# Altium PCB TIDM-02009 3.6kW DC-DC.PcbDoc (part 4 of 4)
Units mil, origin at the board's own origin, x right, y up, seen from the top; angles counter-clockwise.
Board outline 11220.47 x 8463 mil, 4 copper layers (Top Layer, Signal Layer 1, Signal Layer 2, Bottom Layer), stack 109.77 mil thick; 298 components, 250 nets, 959 pads, 2937 vias.
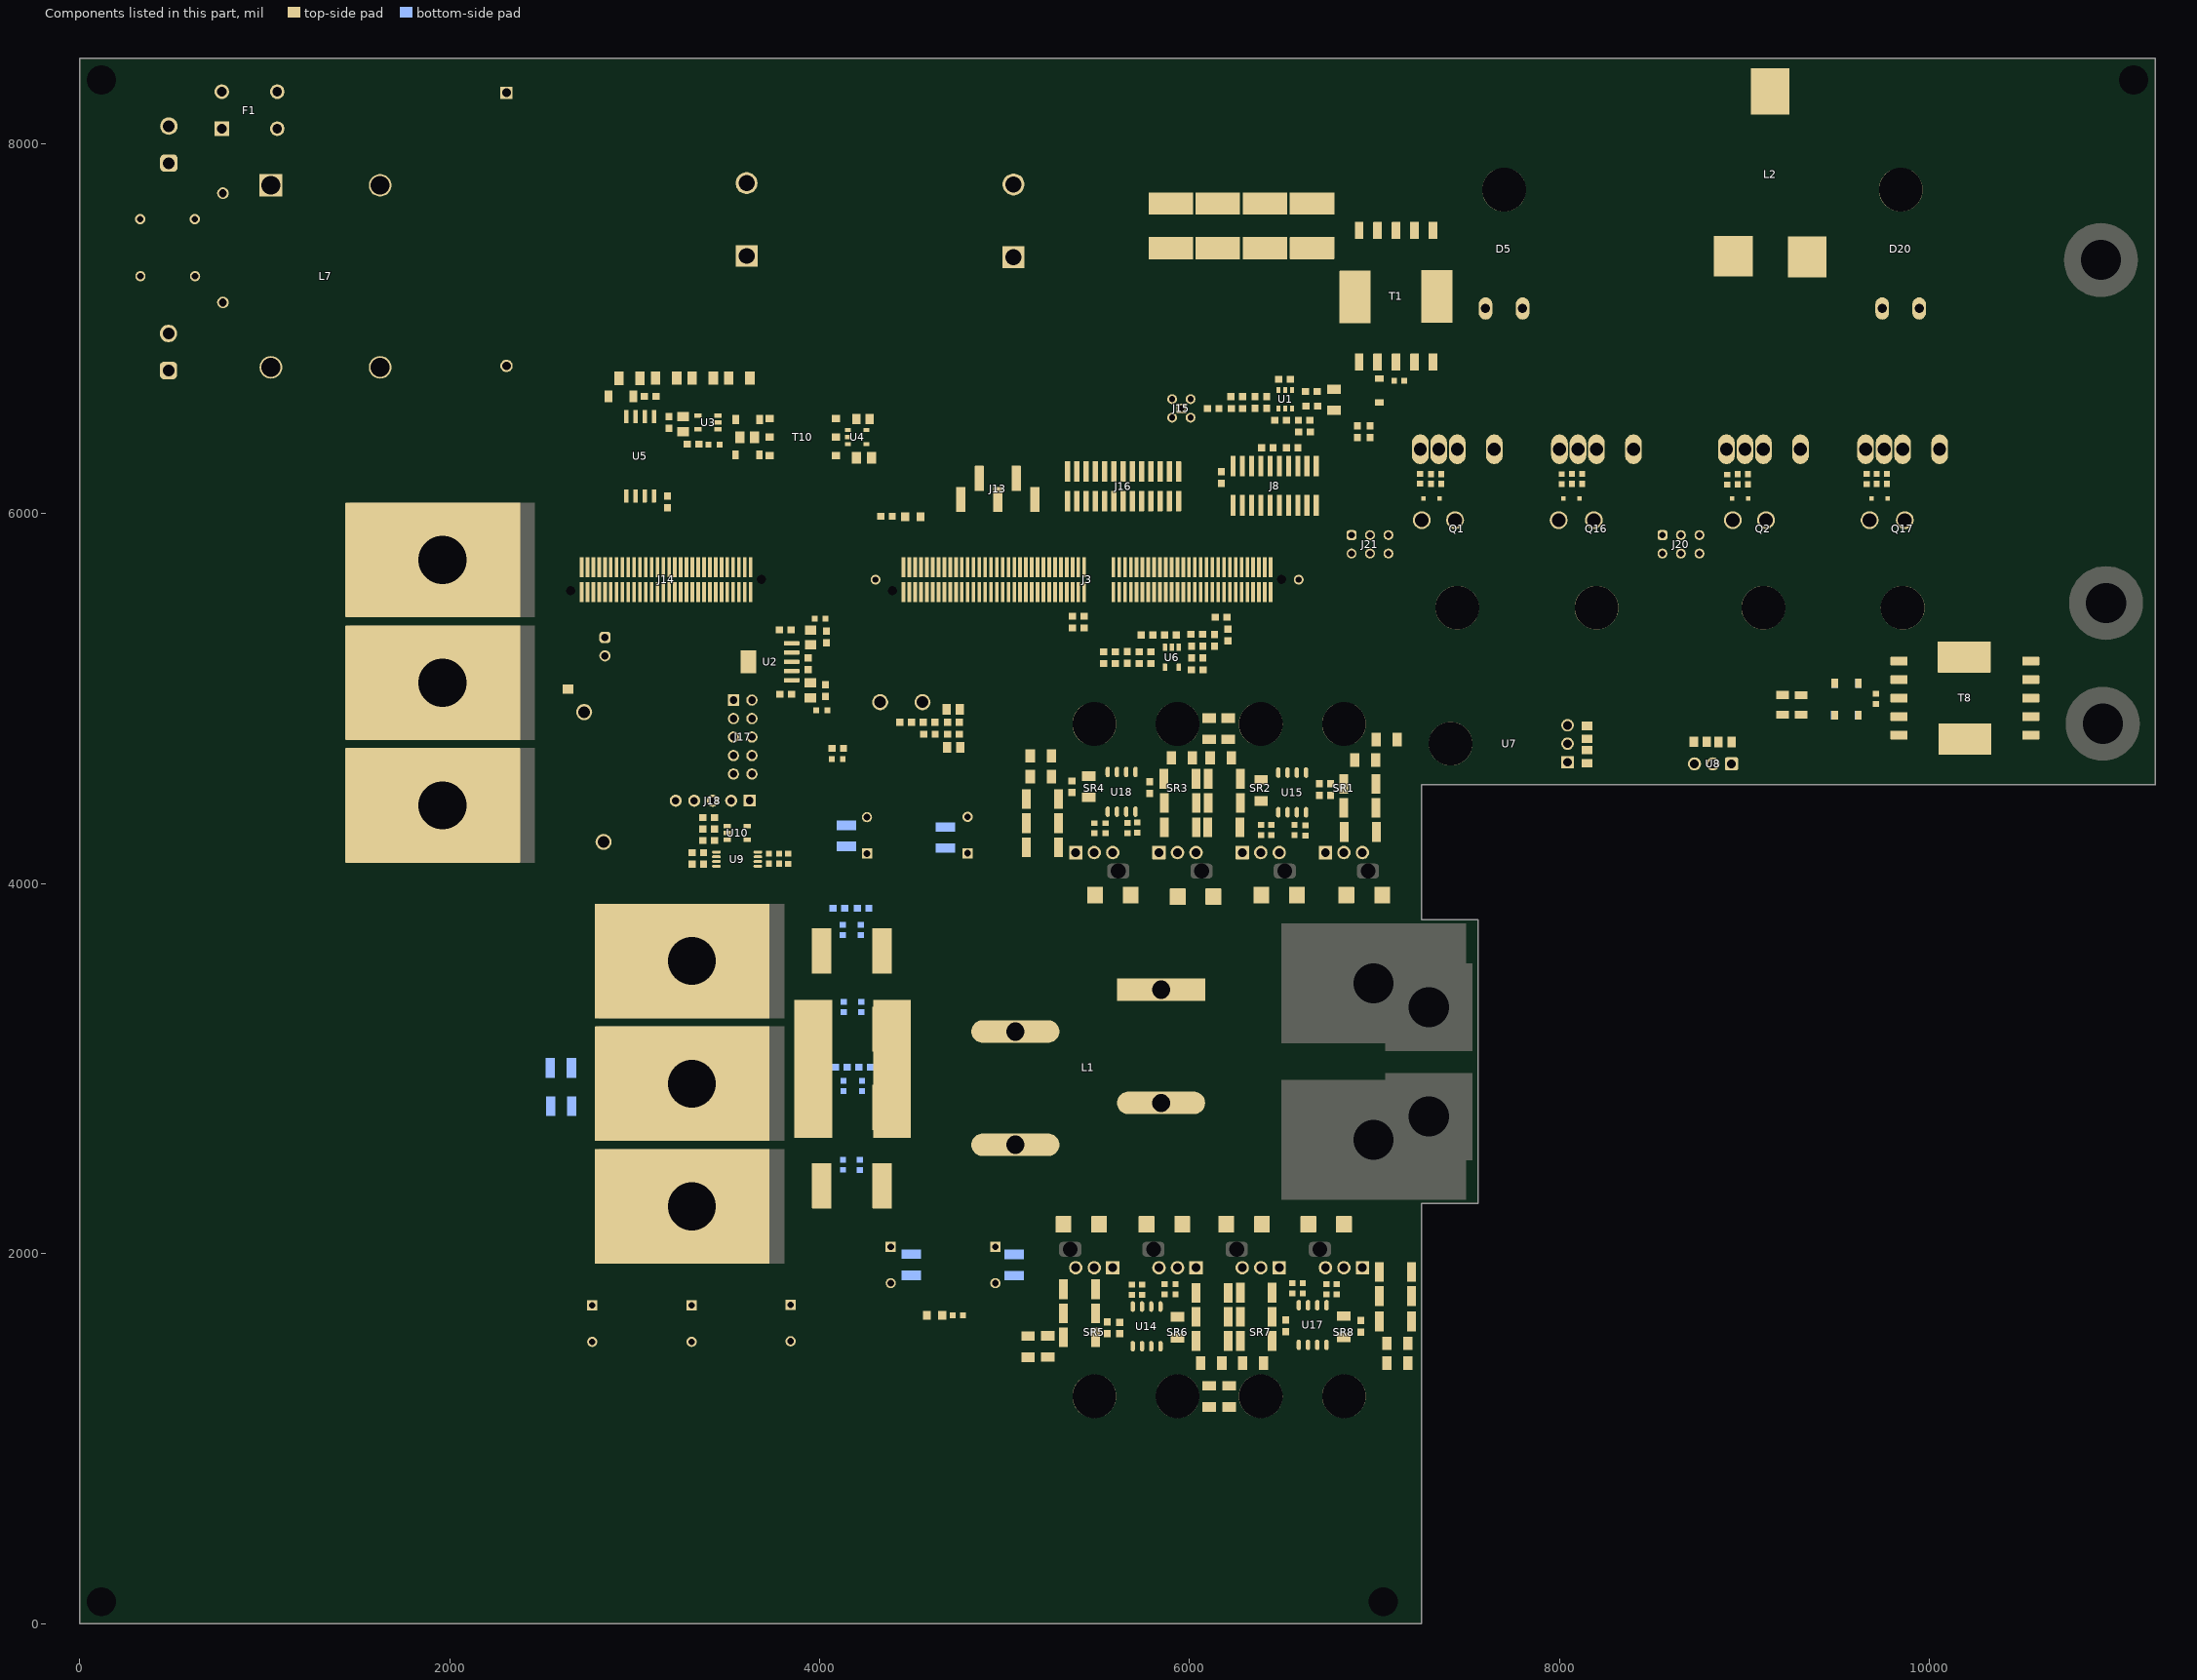
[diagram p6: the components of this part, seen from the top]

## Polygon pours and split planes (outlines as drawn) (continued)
Batt+ on Signal Layer 2 "SIGNAL_LAYER_2_BATT+_P411" (solid, remove dead copper, pour order 411): 288.5,7881.5 380,7790 572,7790 838,8056 838,8357 394.5,8357 288.5,8251
isoGND on Signal Layer 2 "SIGNAL_LAYER_2_ISOGND_P376" (solid, remove dead copper, pour order 376): 1527,7062 1951,7486 2423,7486 2639,7270 2586,7217 2586,6781 2481,6676 1527,6676
isoGND on Signal Layer 2 "SIGNAL_LAYER_2_ISOGND_P301" (solid, pour order 301): 1561,6676 1561,7097 2846,8382 6789,8382 6789,7617 3122,7617 2181,6676
PGND on Signal Layer 2 "SIGNAL_LAYER_2_PGND_P350" (solid, remove dead copper, pour order 350): 4042,1252 4042,1598 4346,1902 5138,1902 5308,2072 5412,2072 5422,2062 5422,1839 5436,1825 5673,1825 5741,1893 5741,2056 5756.99,2071.99 5856,2072 5874,2054 5874,1834 5883,1825 6109,1825 6192,1908 6192,2056 6208,2072 6304,2072 6323,2053 6323,1825 6561,1825 6638,1902 6638,2055 6655,2072 6756,2072 6772,2056 6772,1845 6792,1825 7099,1825 7201,1723 7201,1511 7124,1434 7110,1448 4920,1448 4501,1029 4278,1252
PGND on Signal Layer 2 "SIGNAL_LAYER_2_PGND_P346" (solid, remove dead copper, pour order 346): 5547,4225.22 5485.22,4287 5608.22,4410 7052,4410 7185,4277 7185,4028 7152,3995 6936,3995 6898,4033 6898,4234 6833,4299 6681.67,4299 6592,4209.33 6592,4040 6575,4023 6460,4023 6446,4037 6446,4233 6388,4291 6249,4291 6173,4215 6173,4050 6146,4023 6015,4023 5998,4040 5998,4242.67 5948,4292.67 5786.67,4292.67 5688,4194 5688,4045 5666,4023 5561,4023 5547,4037
PGND on Signal Layer 2 "SIGNAL_LAYER_2_PGND_P283" (solid, pour order 283): 4406,1559 4324,1641 2710,1641 2568,1783 2568,3978 2699,4109 3988,4109 4156,4277 5283.06,4277 7185,4277 7185,5162 6233,6114 207,6114 30,5937 30,149 150,29 7101,29 7201,129 7201,1559
NetD10_2 on Signal Layer 2 "SIGNAL_LAYER_2_NETD10_2_P338" (solid, remove dead copper, pour order 338): 5448,2883.28 5531,2966.28 7509,2966.28 7536,2939.28 7536,2316.28 7503,2283.28 7137,2283.28 6871,2017.28 6871,1893.28 6853,1875.28 6807,1875.28 6797,1885.28 6797,1924.28 6798,1925.28 6798,2066.28 6762,2102.28 6542,2102.28 6422,1982.28 6422,1883.28 6413,1874.28 6358,1874.28 6348,1884.28 6348,2070.28 6318,2100.28 6082,2100.28 5972,1990.28 5972,1889.28 5961,1878.28 5912,1878.28 5898,1892.28 5898,2065.28 5864,2099.28 5638,2099.28 5522,1983.28 5522,1886.28 5514,1878.28 5459,1878.28 5448,1889.28
NetD6_1 on Signal Layer 2 "SIGNAL_LAYER_2_NETD6_1_P327" (solid, remove dead copper, pour order 327): 5449,3163 5500,3112 7496,3112 7532,3148 7532,3766 7508,3790 7080,3790 6870,4000 6870,4203 6860,4213 6803,4213 6797,4207 6797,4109 6777,4089 6683,3995 6444,3995 6421,4018 6421,4203 6411,4213 6353,4213 6346,4206 6346,4109 6233,3996 5995,3996 5971,4020 5971,4204 5963,4212 5904,4212 5895,4203 5895,4104 5788,3997 5543,3997 5521,4019 5521,4202 5512,4211 5455,4211 5449,4205
Io_+ on Signal Layer 2 "SIGNAL_LAYER_2_IO_+_P291" (solid, pour order 291): 4291,2805.44 4291,4026.44 4212,4105.44 4212,4178.44 4236,4202.44 4850,4202.44 5305,3747.44 5305,2317.44 4971,1983.44 4366,1983.44 4290,2059.44 4290,2805.44
S_4 on Signal Layer 2 "SIGNAL_LAYER_2_S_4_P279" (solid, pour order 279): 9589,6175 9659,6245 9806,6245 9946,6105 9946,5913 9900,5867 9589,5867
S_3 on Signal Layer 2 "SIGNAL_LAYER_2_S_3_P278" (solid, pour order 278): 8870,6219 8886,6235 9134,6235 9189,6180 9189,5921 9164.44,5896.44 8870,5896.44
S_2 on Signal Layer 2 "SIGNAL_LAYER_2_S_2_P277" (solid, pour order 277): 7898,6175 7966,6243 8170,6243 8257,6156 8257,5931 8201,5875 7898,5875
S_1 on Signal Layer 2 "SIGNAL_LAYER_2_S_1_P276" (solid, pour order 276): 7180,6240 7418,6240 7517,6141 7517,5973 7438,5894 7180,5894
NetQ2_2 on Signal Layer 2 "SIGNAL_LAYER_2_NETQ2_2_P270" (solid, pour order 270): 9034,6290 9034,6675 9162,6803 10989,6803 11174,6618 11174,5291 10555,5291 10479,5367 10479,5806 10009,6276 10009,6486.21 9963,6532.21 9247.21,6532.21 9143,6428 9143,6289 9119,6265 9072,6265 9058,6279
NetT6_1 on Signal Layer 2 "SIGNAL_LAYER_2_NETT6_1_P267" (solid, pour order 267): 10048,4625 10096,4577 11078,4577 11176,4675 11176,5027 11102,5101 10630,5101 10435,4906 10081,4906 10048,4873
isoGND on Signal Layer 1 "SIGNAL_LAYER_1_ISOGND_P463" (solid, remove dead copper, pour order 463): 2913,6571 2871,6529 2871,6402 2931,6342 3367,6342 3426,6283 3760,6283 3784,6307 3784,6530 3743,6571
AGND on Signal Layer 1 "SIGNAL_LAYER_1_AGND_P461" (solid, pour order 461): 3951,6156 4044,6249 4044,6578 4190,6724 6038,6724 6154,6840 7221,6840 7261,6800 7261,6686 7186,6611 7068,6611 7020,6563 7020,6246 7017.69,5911.31 7180,5749 8385,5749 8566,5930 8724,5930 8811,5843 8811,5385 9002,5194 9655,5194 9759,5090 9759,4772 9572,4585 7185,4585 7185,4244 4122,4244 3923,4045 2647,4045 2647,6183 2687,6223 3238.07,6223 3303.81,6156
PGND on Signal Layer 1 "SIGNAL_LAYER_1_PGND_P459" (solid, pour order 459): 4412,1274 4047,1639 2712.52,1639 2564,1787.52 2564,5548.73 2564,6013 2415,6162 240,6162 27,5949 27,184.11 177.11,34 4274,34 4412,172
12Vout on Signal Layer 1 "SIGNAL_LAYER_1_12VOUT_P453" (solid, remove dead copper, pour order 453): 4069,1723 4027,1681 2732,1681 2628,1785 2628,3951 2703,4026 3817,4026 4069,3774
NetL2_1 on Signal Layer 1 "SIGNAL_LAYER_1_NETL2_1_P445" (solid, remove dead copper, pour order 445): 7402,6894 7402,6281.69 7420.69,6263 7478,6263 7492,6277 7492,6515 7580,6603 8323,6603 8351,6575 8351,6283 8381,6253 8444,6253 8533,6342 8533,7021 9135,7623 9135,8050 9034,8151 8303,8151 8001,7849 8001,7493
Dbus+ on Signal Layer 1 "SIGNAL_LAYER_1_DBUS+_P433" (solid, remove dead copper, pour order 433): 3021,6903 2868,6903 2854,6917 2854,7672 2950,7768 3007,7768 3281,7493 6636,7493 6990,7139 6990,7031 6961,7002 6055,7002 5956,6903
isoGND on Signal Layer 1 "SIGNAL_LAYER_1_ISOGND_P429" (solid, remove dead copper, pour order 429): 3331,7731 3331,8096 3609,8374 6724,8374 6789,8309 6789,7769 6647,7627 3442,7627 3336,7733
Batt- on Signal Layer 1 "SIGNAL_LAYER_1_BATT-_P417" (solid, pour order 417): 282,6723 295,6710 1163,6710 1184,6731 1184,6924 799,7309 595,7309 577,7291 577,7183 282,6888
NetC5_1 on Signal Layer 1 "SIGNAL_LAYER_1_NETC5_1_P413" (solid, remove dead copper, pour order 413): 571,7597 571,7566 607,7530 931,7530 933,7532 1143,7532 1207,7596 1207,8303 1156,8354 1014,8354 966,8306 966,7990 572,7596 569,7596
Batt+ on Signal Layer 1 "SIGNAL_LAYER_1_BATT+_P409" (solid, remove dead copper, pour order 409): 287.25,8249 287.25,7883.75 380,7791 570,7791 837,8058 837,8356 392,8356 286,8250
Dbus+ on Signal Layer 1 "SIGNAL_LAYER_1_DBUS+_P382" (solid, remove dead copper, pour order 382): 1531,8240 1691,8400 2722,8400 3145,7977 3145,6906 2865,6906 2487,7284 1708,7284 1532,7460 1532,8236
AGND on Signal Layer 1 "SIGNAL_LAYER_1_AGND_P344" (solid, remove dead copper, pour order 344): 4265.51,2060 4265.51,1825.74 4394.25,1697 5522,1697 5655,1830 6960.3,1830 7098,1692.3 7098,734 6942,578 5151,578 4088.49,1640.51 4088.49,1994.51
NetD10_2 on Signal Layer 1 "SIGNAL_LAYER_1_NETD10_2_P334" (solid, remove dead copper, pour order 334): 5448,2883 5531,2966 7509,2966 7536,2939 7536,2316 7503,2283 7137,2283 6871,2017 6871,1893 6853,1875 6807,1875 6797,1885 6797,1924 6798,1925 6798,2080 6776,2102 6542,2102 6422,1982 6422,1883 6413,1874 6358,1874 6348,1884 6348,2076 6324,2100 6082,2100 5972,1990 5972,1889 5961,1878 5912,1878 5898,1892 5898,2079 5878,2099 5638,2099 5522,1983 5522,1886 5514,1878 5459,1878 5448,1889
NetD6_1 on Signal Layer 1 "SIGNAL_LAYER_1_NETD6_1_P329" (solid, remove dead copper, pour order 329): 5449,3163 5500,3112 7496,3112 7532,3148 7532,3766 7508,3790 7080,3790 6870,4000 6870,4203 6860,4213 6803,4213 6797,4207 6797,4109 6777,4089 6683,3995 6444,3995 6421,4018 6421,4203 6411,4213 6353,4213 6346,4206 6346,4109 6233,3996 5990,3996 5971,4015 5971,4204 5963,4212 5904,4212 5895,4203 5895,4104 5788,3997 5538,3997 5521,4014 5521,4202 5512,4211 5455,4211 5449,4205
Io_+ on Signal Layer 1 "SIGNAL_LAYER_1_IO_+_P290" (solid, pour order 290): 4292,2806 4292,4027 4213,4106 4213,4179 4237,4203 4851,4203 5306,3748 5306,2318 4972,1984 4367,1984 4291,2060 4291,2806
AGND on Signal Layer 1 "SIGNAL_LAYER_1_AGND_P272" (solid, pour order 272): 3753.67,4119.33 4087,3786 4087,1996 4133,1950 4199,1950 4219,1970 4219,2011 4266,2058 4266,3976 4132.99,4109.01 4132.99,4262 3883,4262 3727,4106
NetT6_1 on Signal Layer 1 "SIGNAL_LAYER_1_NETT6_1_P268" (solid, pour order 268): 10052,4621 10096,4577 11078,4577 11176,4675 11176,5027 11098,5105 10634,5105 10435,4906 10081,4906 10052,4877
NetQ2_2 on Signal Layer 1 "SIGNAL_LAYER_1_NETQ2_2_P266" (solid, pour order 266): 9057,6324 9057,6812 9185,6940 11105,6940 11185,6860 11185,5285 10563,5285 10485,5363 10485,5801 10057,6229 10008,6278 10008,6488 9967,6529 9295,6529 9164,6398 9164,6291 9137,6264 9076,6264 9056,6284 9056,6326
12Vout on Top Layer "TOP_LAYER_12VOUT_P451" (solid, remove dead copper, pour order 451): 4069,1723 4027,1681 2732,1681 2631,1782 2631,3951 2706,4026 3817,4026 4069,3774
NetL2_1 on Top Layer "TOP_LAYER_NETL2_1_P443" (solid, remove dead copper, pour order 443): 9079,7260 8820,7260 8757,7323 8486,7594 8486,7890 8641,8045 9043,8045 9079,8009
NetD5_1 on Top Layer "TOP_LAYER_NETD5_1_P441" (solid, remove dead copper, pour order 441): 7617,6264 7593,6288 7593,6835 7428,7000 7271,7000 7248,7023 7248,7352 7247,7353 7373,7479 8322,7479 8546,7255 8778,7023 9016,7023 9483,6556 9483,6268 9471.09,6256.09 9276.93,6256.07 9253,6280 9253,6480 9219,6514 7926,6514 7810,6398 7810,6286 7788,6264
isoGND on Top Layer "TOP_LAYER_ISOGND_P427" (solid, remove dead copper, pour order 427): 6788,7615 3441,7615 3334,7722 3334,8102 3610,8378 6731,8378 6788,8321
Dbus+ on Top Layer "TOP_LAYER_DBUS+_P423" (solid, remove dead copper, pour order 423): 2929,6904 2869,6904 2833,6940 2833,7775 2917,7859 3282,7494 6796,7494 6990,7300 6990,7032 6961,7003 6060,7003 5961,6904
Dbus+ on Top Layer "TOP_LAYER_DBUS+_P380" (solid, remove dead copper, pour order 380): 1527,8246 1682,8401 2722,8401 3146,7977 3146,6907 2866,6907 2488,7285 1712,7285 1527,7470
PGND on Top Layer "TOP_LAYER_PGND_P370" (solid, remove dead copper, pour order 370): 6898,4162 6898,4198 6912,4212 7021,4212 7095,4138 7095,3904 7081,3890 7080,3891 7003,3891 6997,3897 6997,3933 6899,4031 6899,4162
PGND on Top Layer "TOP_LAYER_PGND_P368" (solid, remove dead copper, pour order 368): 6446.52,4196.52 6460,4210 6561.87,4210 6608.67,4163.2 6608.67,4067.76 6580.85,4039.94 6580.85,4006 6569,4006 6551,4024 6460,4024 6446.52,4037.48
PGND on Top Layer "TOP_LAYER_PGND_P366" (solid, remove dead copper, pour order 366): 5998.98,4147 5998.98,4197.98 6011,4210 6112.46,4210 6158,4164.46 6158,4126 6140,4108 6140,4028 6117,4005 6117,4006 6100,4023 6008,4023 5998,4033 5998,4147
PGND on Top Layer "TOP_LAYER_PGND_P364" (solid, remove dead copper, pour order 364): 5547,4190.04 5566.96,4210 5664,4210 5711,4163 5711,4076 5689,4054 5689,4030 5665,4006 5646,4025 5564,4025 5547,4042
PGND on Top Layer "TOP_LAYER_PGND_P362" (solid, remove dead copper, pour order 362): 6771,2053 6752,2072 6691,2072 6674,2089 6629,2044 6629,1910.85 6654.57,1885.28 6768.28,1885.28 6771,1888
PGND on Top Layer "TOP_LAYER_PGND_P360" (solid, remove dead copper, pour order 360): 6322,2054 6306,2070 6233,2070 6224,2079 6180,2035 6180,1912 6206.72,1885.28 6314,1885.28 6322,1893.28
PGND on Top Layer "TOP_LAYER_PGND_P358" (solid, remove dead copper, pour order 358): 5857,1885 5873,1901 5873,2053 5855,2071 5784,2071 5778,2077 5729,2028 5729,1910 5754,1885
PGND on Top Layer "TOP_LAYER_PGND_P356" (solid, remove dead copper, pour order 356): 5420,1897 5420,2176 5390,2206 5278,2206 5265,2193 5265,1917 5297,1885 5408,1885
NetD10_2 on Top Layer "TOP_LAYER_NETD10_2_P336" (solid, remove dead copper, pour order 336): 5448,2883.28 5550.72,2986 7536,2986 7536,2316.28 7503,2283.28 7137,2283.28 6871,2017.28 6871,1893.28 6853,1875.28 6807,1875.28 6797,1885.28 6797,1924.28 6798,1925.28 6798,2066.28 6762,2102.28 6542,2102.28 6422,1982.28 6422,1883.28 6413,1874.28 6358,1874.28 6348,1884.28 6348,2070.28 6318,2100.28 6082,2100.28 5972,1990.28 5972,1889.28 5961,1878.28 5912,1878.28 5898,1892.28 5898,2065.28 5864,2099.28 5638,2099.28 5522,1983.28 5522,1886.28 5514,1878.28 5459,1878.28 5448,1889.28
NetD6_1 on Top Layer "TOP_LAYER_NETD6_1_P333" (solid, remove dead copper, pour order 333): 5449,3163 5522,3090 7532,3090 7532,3766 7508,3790 7080,3790 6870,4000 6870,4203 6860,4213 6803,4213 6797,4207 6797,4109 6777,4089 6683,3995 6444,3995 6421,4018 6421,4203 6411,4213 6353,4213 6346,4206 6346,4109 6233,3996 5995,3996 5971,4020 5971,4204 5963,4212 5904,4212 5895,4203 5895,4104 5788,3997 5543,3997 5521,4019 5521,4202 5512,4211 5455,4211 5449,4205
PGND on Top Layer "TOP_LAYER_PGND_P307" (solid, pour order 307): 4412,1274 4047,1639 2712.52,1639 2545.39,1806.13 2545.39,4140.18 2545.39,5692 2545,5695 2545,6032 2415,6162 240,6162 27,5949 27,184.11 177.11,34 4274,34 4412,172
Io_+ on Top Layer "TOP_LAYER_IO_+_P271" (solid, pour order 271): 4282,2806 4282,2062 4370,1974 4980,1974 5043,2037 5043,2091 5305,2353 5305,3673 5127,3851 4852,4126 4852,4177 4810,4219 4238,4219 4211,4192 4211,4108 4281,4038 4281,2805.16
NetD5_2 on Top Layer "TOP_LAYER_NETD5_2_P265" (solid, pour order 265): 10034,5122 10034,5727 10244,5937 10244,6544 10082,6706 9706,6706 9187,7225 9187,7911 9579,8303 10801,8303 11165,7939 11165,6253 10618,5706 10618,5370 10370,5122
NetC5_1 on Top Layer "TOP_LAYER_NETC5_1_P249" (solid, pour order 249): 574,7572 574,7597 966,7989 966,8306 996,8336 1173,8336 1207,8302 1207,7599 1139,7531 605,7531 576,7560 576,7567
Batt- on Top Layer "TOP_LAYER_BATT-_P248" (solid, pour order 248): 287,6723 287,6888 572,7173 572,7278 604,7310 794,7310 1181,6923 1181,6726 1164,6709 286,6709 286,6723
Batt+ on Top Layer "TOP_LAYER_BATT+_P247" (solid, pour order 247): 290,7878 290,8254 372,8336 818,8336 818,8041 570,7793 377,7793 289,7881
12Vout on Bottom Layer "BOTTOM_LAYER_12VOUT_P457" (solid, remove dead copper, pour order 457): 4069,1723 4027,1681 2732,1681 2625,1788 2625,3949 2702,4026 3817,4026 4069,3774
PGND on Bottom Layer "BOTTOM_LAYER_PGND_P447" (solid, remove dead copper, pour order 447): 2573,3985 2573,1782 2716,1639 4083,1639 4346,1902 5138,1902 5308,2072 5411,2072 5421.67,2061.33 5421.67,1839 5435.67,1825 5672.67,1825 5738,1890.33 5738,2056 5754,2072 5854,2072 5873.67,2052.33 5873.67,1834 5882.67,1825 6108.67,1825 6185,1901.33 6185,2048 6209,2072 6303,2072 6322.67,2052.33 6322.67,1825 6560.67,1825 6637.67,1902 6637.67,2054.67 6655,2072 6756.47,2072 6771.67,2056.8 6771.67,1845 6791.67,1825 7098.67,1825 7200.67,1723 7200.67,1511 7198,1508.33 7198,128 7098,28 147,28 27,148 27,5940 249,6162 3335,6162 6349,6162 7182,5329 7182,4256 3789,4256 3641,4108 2696,4108
Dbus+ on Bottom Layer "BOTTOM_LAYER_DBUS+_P425" (solid, pour order 425): 3015,6951 3015,7225 3283,7493 6602,7493 6991,7104 6991,7031 6962,7002 6045,7002 5946,6903 3022,6903 3016,6909 3016,6950
isoGND on Bottom Layer "BOTTOM_LAYER_ISOGND_P397" (solid, remove dead copper, pour order 397): 1528,7059 1953,7484 2584,7484 2673,7395 2585.5,7307.5 2585.5,6781.5 2483,6679 1528,6679
isoGND on Bottom Layer "BOTTOM_LAYER_ISOGND_P273" (solid, pour order 273): 2194,6687 3116,7609 6683,7609 7692,6600 8121,6600 8157,6564 8157,6299 8190,6266 8226,6266 8245,6285 8244.99,6523.99 8321,6600 9708,6600 9809,6499 9809,6284 9828,6265 9884,6265 9907,6288 9906,6289 9906,6496 10059,6649 10059,7360 9899,7520 7651,7520 6789,8382 2846,8382 1567,7103 1567,6687
PGND on Bottom Layer "BOTTOM_LAYER_PGND_P378" (solid, remove dead copper, pour order 378): 5547,4225.22 5485.22,4287 5608.22,4410 7052,4410 7185,4277 7185,4028 7152,3995 6936,3995 6898,4033 6898,4234 6833,4299 6681.67,4299 6592,4209.33 6592,4038 6577,4023 6460,4023 6446,4037 6446,4233 6388,4291 6249,4291 6173,4215 6173,4050 6146,4023 6016,4023 5998,4041 5998,4242.67 5948,4292.67 5786.67,4292.67 5688,4194 5688,4045 5666,4023 5558,4023 5547,4034
NetD10_2 on Bottom Layer "BOTTOM_LAYER_NETD10_2_P354" (solid, remove dead copper, pour order 354): 5448,2883.47 5531,2966.47 7509,2966.47 7536,2939.47 7536,2316.47 7503,2283.47 7137,2283.47 6871,2017.47 6871,1893.47 6853,1875.47 6807,1875.47 6797,1885.47 6797,1924.47 6798,1925.47 6798,2066.47 6762,2102.47 6542,2102.47 6422,1982.47 6422,1883.47 6413,1874.47 6358,1874.47 6348,1884.47 6348,2070.47 6318,2100.47 6082,2100.47 5972,1990.47 5972,1889.47 5961,1878.47 5912,1878.47 5898,1892.47 5898,2065.47 5864,2099.47 5638,2099.47 5522,1983.47 5522,1886.47 5514,1878.47 5459,1878.47 5448,1889.47
NetD6_1 on Bottom Layer "BOTTOM_LAYER_NETD6_1_P348" (solid, remove dead copper, pour order 348): 5449,3162.9 5500,3111.9 7496,3111.9 7532,3147.9 7532,3765.9 7508,3789.9 7080,3789.9 6870,3999.9 6870,4202.9 6860,4212.9 6803,4212.9 6797,4206.9 6797,4108.9 6777,4088.9 6683,3994.9 6444,3994.9 6421,4017.9 6421,4202.9 6411,4212.9 6353,4212.9 6346,4205.9 6346,4108.9 6233,3995.9 5995,3995.9 5971,4019.9 5971,4203.9 5963,4211.9 5904,4211.9 5895,4202.9 5895,4103.9 5788,3996.9 5543,3996.9 5521,4018.9 5521,4201.9 5512,4210.9 5455,4210.9 5449,4204.9
S_4 on Bottom Layer "BOTTOM_LAYER_S_4_P340" (solid, pour order 340): 9589,6175 9659,6245 9806,6245 9946,6105 9946,5913 9900,5867 9589,5867
S_3 on Bottom Layer "BOTTOM_LAYER_S_3_P331" (solid, pour order 331): 8870,6219 8886,6235 9134,6235 9189,6180 9189,5921 9164.44,5896.44 8870,5896.44
S_2 on Bottom Layer "BOTTOM_LAYER_S_2_P325" (solid, pour order 325): 7898,6175 7966,6243 8170,6243 8257,6156 8257,5931 8201,5875 7898,5875
S_1 on Bottom Layer "BOTTOM_LAYER_S_1_P323" (solid, pour order 323): 7180,6240 7418,6240 7517,6141 7517,5973 7438,5894 7180,5894
PGND on Bottom Layer "BOTTOM_LAYER_PGND_P321" (solid, remove dead copper, pour order 321): 3734.93,4240 4022,4240 4150,4368 4130.92,4387.08 3801,4387.08 3801,4309.07 3734.93,4243
NetC5_1 on Bottom Layer "BOTTOM_LAYER_NETC5_1_P297" (solid, pour order 297): 570,7597 963,7990 963,8305 995,8337 1172,8337 1210,8299 1210,7599 1144,7533 588,7533 570,7551
Batt- on Bottom Layer "BOTTOM_LAYER_BATT-_P296" (solid, pour order 296): 282,6739 315,6706 1163,6706 1186,6729 1186,6934 811,7309 596,7309 566,7279 566,7178 282,6894
Batt+ on Bottom Layer "BOTTOM_LAYER_BATT+_P282" (solid, pour order 282): 294,7886 391,7789 587,7789 817,8019 817,8335 373,8335 294,8256
Io_+ on Bottom Layer "BOTTOM_LAYER_IO_+_P281" (solid, pour order 281): 4286,3099 4331,3054 4331,2960 4284,2913 4284,2059.09 4373.09,1970 5104,1970 5164,2030 5164,2173 5305,2314 5305,3733 4855,4183 4813,4225 4091,4225 4078,4212 4078,4145 4188,4035 4234,4035 4320,3949 4320,3820 4286,3786
NetT6_1 on Bottom Layer "BOTTOM_LAYER_NETT6_1_P274" (solid, pour order 274): 10051,4623 10096,4578 11078,4578 11176,4676 11176,5028 11101,5103 10631,5103 10435,4907 10081,4907 10051,4877
Dbus+ on Bottom Solder "TOP_LAYER_NONET_P437" (solid, pour order 437): 3015,6952 3015,7226 3283,7494 6635,7494 6991,7138 6991,7032 6962,7003 6051,7003 5952,6904 3022,6904 3016,6910 3016,6951
isoGND on Bottom Solder "BOTTOM_LAYER_GND_P407" (solid, pour order 407): 1568,6901 1568,7098 1954,7484 2585,7484 2674,7395 2586.5,7307.5 2586.5,6781.5 2484,6679 1566,6679 1566,6899
isoGND on Bottom Solder "BOTTOM_LAYER_GND_P405" (solid, pour order 405): 2194,6687 3122,7615 6677,7615 7692,6600 8121,6600 8157,6564 8157,6288 8179,6266 8226,6266 8245,6285 8244.99,6523.99 8321,6600 9708,6600 9809,6499 9809,6284 9828,6265 9884,6265 9907,6288 9906,6289 9906,6496 10059,6649 10059,7360 9899,7520 7651,7520 6793,8378 2851,8378 1567,7094 1567,6687
AGND on Bottom Solder "TOP_LAYER_AGND_P226" (solid, pour order 226): 2544,5697 2544,6034 2414,6164 239,6164 26,5951 26,353 343,36 4273,36 4411,174 4411,1277 4260,1428 2471,1428 2471,4020 2544.39,4093.39 2544.39,5694

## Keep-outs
Keep-Out Layer:
  lines w20: 11220.47,4534.85 7254.39,4534.85 7254.39,3806.5 7560,3806.5 7560,2271.07 7254.39,2271.07 ; 11220.47,8463 0,8463 0,0 7254.39,0 7254.39,2271.07 ; 7254.39,2271.07 7254.39,2271.07 ; 11220.47,0 11220.47,0
  text ".Layer_Name" at 577,-858.49 h60

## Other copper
Top Layer:
  region net AGND: 2742.12,5087 2647.6,5087 2647.6,5017 2742.12,5017
  region net PGND: 2628.6,5087 2537.6,5087 2537.6,5017 2628.6,5017
  rectangle net Earth: 273,7191 406,7652
  region net AGND: 3515,5332 3515,5071 3720,5071 3720,5332
  text ".Layer_Name" at 577,-858.49 h60
Signal Layer 1:
  rectangle net PGND: 6639,1879 6770,2068
  rectangle net PGND: 6189,1887 6322,2067
  rectangle net PGND: 5741,1887 5871,2067
  rectangle net PGND: 5286,1884 5422,2077
  rectangle net PGND: 6899.45,4021 7036,4209
  rectangle net PGND: 6449,4026 6583,4208
  rectangle net PGND: 5999,4022 6132,4210
  rectangle net PGND: 5549,4024 5682,4210
  rectangle net NetQ2_2: 9057,6264 9137,6427.05
  region net NetL2_1: 7478,6263 7420.69,6263 7402,6281.7 7402,6441 7492,6441 7492,6277
  text ".Layer_Name" at 577,-858.49 h60
Signal Layer 2:
  rectangle net NetQ2_2: 9056,6265 9143,6428
  text ".Layer_Name" at 577,-858.49 h60
Bottom Layer:
  rectangle net isoGND: 8157,6266 8245,6424.07
  rectangle net isoGND: 9809,6265 9884,6427.59
  rectangle net isoGND: 8160,6266 8239,6425.29
  rectangle net Earth: 269,7191 406,7652
  text ".Layer_Name" at 577,-858.49 h60

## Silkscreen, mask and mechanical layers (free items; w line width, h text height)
Top Overlay:
  region: 1858,594 1558,594 1558,494 1858,494
  text "HV+" at 413,8267 h72.83
  text "Terminal 2'" at 10528,7637 h60
  text "High Voltage Danger" at 9956,6572 h60
  text "HV-" at 401.56,6548 h72.83
  text "LV_GND" at 1828,6144 h72.83
  text "Terminal 1" at 10599,5746 h60
  text "5Vs" at 3315,4969 h72.83
  text "GND" at 3307.01,4865.73 h72.83
  text "5V_IPS" at 3234,4770 h72.83
  text "GND" at 3311,4662 h72.83
  text "Terminal 2" at 10372,4583 h60
  text "12V" at 3340.08,4567.08 h72.83
  text "LV_12V" at 3171,3934 h72.83
  text "'.PRJ_Number'.PCB_Rev-" at 859,509 h108.27
  text "400V-12V, 3.6kW DC-DC Converter" at 510,113 h130 r90
  text ".Layer_Name" at 577,-858.49 h60
Bottom Overlay:
  text ".Layer_Name" at 577,-858.49 h60
Top Paste:
  text ".Layer_Name" at 577,-858.49 h60
Bottom Paste:
  text ".Layer_Name" at 577,-858.49 h60
Top Solder:
  text ".Layer_Name" at 577,-858.49 h60
  text ".Layer_Name" at 577,-858.49 h60
Bottom Solder:
  text ".Layer_Name" at 577,-858.49 h60
Drill Guide:
  text ".Layer_Name" at 577,-858.49 h60
M1 Board Outline:
  lines w20: 7254.39,2271.07 7560,2271.07 7560,3806.5 7254.39,3806.5 7254.39,4534.85 11220.47,4534.85 11220.47,8463 0,8463 0,0 7254.39,0 7254.39,2271.07 ; 7254.39,2271.07 7254.39,2271.07 ; 11220.47,0 11220.47,0
  text ".Layer_Name" at 577,-858.49 h60
M2 Board Dimensions:
  rectangle: 0,-275 125,-150
  rectangle: 125,-400 500,-275
  lines w7: 0,-275 1000,-275 ; 125,-400 125,-150 ; 250,-400 250,-150 ; 500,-400 500,-150 ; 750,-400 750,-150 ; 0,-400 1000,-400 1000,-150 0,-150 0,-400
  text ".Layer_Name" at 577,-858.49 h60
M3 3D STEP Top:
  text ".Layer_Name" at 577,-858.49 h60
M4 3D STEP Bottom:
  text ".Layer_Name" at 577,-858.49 h60
M5 Assembly Top:
  lines w10: -292,-930.17 6308,-930.17 ; -292,-726.83 6310,-726.83 ; -292,-523.5 -292,-1133.5 3713,-1133.5 6310,-1133.5 6310,-523.5 -291.5,-523.5 -291.5,-1133.5 1284,-1133.5 ; 2173,-1133.5 2173,-523.5 ; 3440,-726.83 3440,-523.5 ; 4280,-726.83 4280,-523.5 ; 4902,-1140 4902,-937.17
  text "COMPONENTS MARKED 'DNP' SHOULD NOT BE POPULATED." at 1153.5,-318.5 h30
  text "ASSEMBLY VARIANT:" at 1153,-434 h30
  text ".VariantName" at 2189,-434 h30
  text "PCB VIEWED FROM TOP SIDE" at -228.5,-655.67 h60
  text "BOARD #:" at 2248,-655.67 h60
  text ".PRJ_Number" at 2793.5,-655.67 h60
  text "REV:" at 3638,-655.67 h60
  text ".PCB_Rev" at 3929.5,-655.67 h60
  text "SVN REV:" at 4476,-655.67 h60
  text ".VersionControl_RevNumber" at 4982,-655.67 h60
  text "TID #:" at 2248,-859 h60
  text ".TID" at 2793.5,-859 h60
  text "PLOT NAME =" at -228.5,-1064.34 h60
  text ".plot_File_Name" at 577,-1064.34 h60
  text "GENERATED    :" at 2250,-1064.34 h60
  text ".Print_Date" at 3119.5,-1064.34 h60
  text ".Print_Time" at 3848.5,-1064.34 h60
  text "TEXAS INSTRUMENTS" at 5113,-1064.34 h60
M6 Assembly Bottom:
  lines w10: -292.5,-727.33 6309.5,-727.33 ; -290.5,-930.67 6309.5,-930.67 ; 1115.5,-1140.5 1115.5,-937.67 ; 1737.5,-727.33 1737.5,-524 ; 2577.5,-727.33 2577.5,-524 ; 3844.5,-1134 3844.5,-524 ; 4733.5,-1134 6309,-1134 6309,-524 -292.5,-524 -292.5,-1134 2304.5,-1134 6309.5,-1134 6309.5,-524
  lines w30: 2458.13,4063.59 2458.13,6071.33 ; 5206.01,4063.58 5206.01,5835.11 3237.62,5835.11 3237.62,6071.33 1426.6,6071.33 1426.6,4063.46 3867.54,4063.46 3867.54,2016.22 7095.89,2016.22 7095.89,2272.13 6570.53,2272.13 6570.53,3768.19 7095.89,3768.19 7095.89,4063.46 5206.13,4063.46
  text "COMPONENTS MARKED 'DNP' SHOULD NOT BE POPULATED." at 6102,-318 h30
  text ".VariantName" at 5058,-434 h30
  text "ASSEMBLY VARIANT:" at 6097,-434 h30
  text ".VersionControl_RevNumber" at 1035.5,-656.17 h60
  text "SVN REV:" at 1541.5,-656.17 h60
  text ".PCB_Rev" at 2088,-656.17 h60
  text "REV:" at 2379.5,-656.17 h60
  text ".PRJ_Number" at 3224,-656.17 h60
  text "BOARD #:" at 3769.5,-656.17 h60
  text "PCB VIEWED FROM BOTTOM SIDE" at 6246,-656.17 h60
  text ".TID" at 3224,-859.5 h60
  text "TID #:" at 3769.5,-859.5 h60
  text "TEXAS INSTRUMENTS" at 904.5,-1064.84 h60
  text ".Print_Time" at 2169,-1064.84 h60
  text ".Print_Date" at 2898,-1064.84 h60
  text "GENERATED    :" at 3767.5,-1064.84 h60
  text ".plot_File_Name" at 5440.5,-1064.84 h60
  text "PLOT NAME =" at 6246,-1064.84 h60
M9 Title Sheet:
  drawing of 57 lines, arcs and shapes, not listed
  text "1" at 558,9139 h70
  text "2" at 3235.5,9136.5 h70
  text "3" at 5724.84,9136.5 h70
  text "4" at 8231.51,9136.5 h70
  text "5" at 12573.02,9136.5 h70
  text "6" at 15078.02,9136.5 h70
  text "A" at -416.5,7993.5 h70
  text "A" at 17626.02,7993.5 h70
  text "B" at -416.5,4513.5 h70
  text "B" at 17626.02,4513.5 h70
  text "C" at -416.5,2138.5 h70
  text "C" at 17626.02,2138.5 h70
  text "PROJECT TITLE:" at 14586.02,277.5 h45
  text ".PRJ_Title" at 14636.02,144.17 h70
  text "DESIGNED FOR:" at 14586.02,-23.5 h45
  text ".PRJ_Customer" at 14636.02,-163.5 h70
  text "D" at -416.5,-231.5 h70
  text "D" at 17626.02,-231.5 h70
  text "FILE NAME:" at 14586.02,-323.5 h45
  text ".PCB_File_Name_No_Path" at 14636.02,-443.5 h70
  text "Texas Instruments (TI) and/or its licensors do not warrant the accuracy or completeness of this specification" at 9616.52,-605.34 h45
  text "ENGINEER:" at 14586.02,-613.5 h45
  text "LAYOUT BY:" at 16091.02,-613.5 h45
  text "or any information contained therein. TI and/or its licensors do not warrant that this design will meet" at 9571.53,-718 h45
  text ".PRJ_Engineer" at 14636.02,-768.49 h70
  text ".PCB_Layout" at 16141.52,-768.49 h70
  text "the specifications, will be suitable for your application or fit for any particular purpose, or will operate in" at 9571.53,-830.67 h45
  text ".Layer_Name" at 577,-858.49 h60
  text "ALTIUM DESIGNER VERSION:" at 16091.02,-923.5 h45
  text "an implementation. TI and/or its licensors do not warrant that the design is production worthy. You should" at 9571.53,-943.33 h45
  text "completely validate and test your design implementation to confirm the system functionality for your application." at 9616.52,-1056 h45
  text ".print_Scale" at 14636.02,-1056.83 h70
  text ".Application_BuildNumber" at 16141.52,-1056.83 h70
  text "1" at 739.84,-1263.5 h70
  text "2" at 3235.5,-1263.5 h70
  text "3" at 5724.84,-1263.5 h70
  text "4" at 8231.51,-1263.5 h70
  text "5" at 10730.5,-1263.5 h70
  text "6" at 16478.02,-1263.5 h70
M10 Fab Notes:
  drawing of 189 lines, arcs and shapes, not listed
  text "DESIGN INFORMATION" at 15622.02,6375.17 h60
  text "MIN. TRACK WIDTH:" at 14977.46,6243.05 h60
  text "8" at 16073.7,6243.05 h60
  text "MIL" at 16228.46,6243.05 h60
  text "MIN. CLEARANCE:" at 14977.46,6118.92 h60
  text "0.2" at 16013.7,6118.93 h60
  text "mm" at 16228.46,6118.92 h60
  text "MIN. VIA PAD SIZE:" at 14977.46,5994.8 h60
  text "24" at 16043.71,5994.8 h60
  text "MIL" at 16228.46,5994.8 h60
  text "0.05mm (2MIL)" at 15672.46,5864.9 h60
  text "MINIMUM ANNULAR RING" at 14648.23,5856.67 h60
  text "EXTERNAL" at 16380.46,5856.67 h60
  text "PER" at 14848.23,5746.55 h60
  text "IPC-D-275 CLASS 2 LEVEL C" at 15068.23,5746.54 h60
  text "MIL, HOLES" at 16556.46,5646.07 h60
  text "+/-" at 16164,5637.48 h60
  text "+/-" at 17018,5637.48 h60
  text "REGISTRATION TOLERANCES:" at 14648.23,5636.42 h60
  text "METAL" at 15848,5636.42 h60
  text "5" at 16424.2,5636.42 h60
  text "3" at 17257.2,5636.42 h60
  text "MIL" at 17373.46,5636.42 h60
  text "HOLE SIZE TOLERANCE (UNLESS OTHERWISE SPECIFIED):" at 14648.23,5538.1 h60
  text "+/-" at 17018,5535.23 h60
  text "3" at 17257.2,5534.17 h60
  text "MIL" at 17373.46,5534.17 h60
  text "MATERIAL:" at 14573.46,5396.52 h60
  text "FR-4 High Tg" at 15559.9,5268 h60
  text "X" at 15415.46,5260.01 h60
  text "FR-408" at 14994.46,5255.49 h60
  text "OTHER" at 16482.46,5255.49 h60
  text "62 MIL (1.6mm) +/-10%" at 15314.56,5112.46 h60
  text "X" at 15194.46,5110.01 h60
  text "THICKNESS:" at 14648.23,5104.24 h60
  text "OTHER" at 16599.46,5104.24 h60
  text "TOLERANCE:" at 14648.23,4965.92 h60
  text "X" at 15496.46,4965.92 h60
  text "ANSI IPC-6012 TYPE 3 CLASS 2" at 15674.48,4965.92 h60
  text "OTHER +/-" at 15674.46,4821.73 h60
  text "BOW & TWIST:" at 14648.23,4676.54 h60
  text "X" at 15496.46,4676.54 h60
  text "ANSI IPC-6012 TYPE 3 CLASS 2" at 15674.48,4676.54 h60
  text "OTHER +/-" at 15674.46,4529.85 h60
  text "DRILLING:" at 14573.46,4399.23 h60
  text "NC_DRILL FILES" at 16334.46,4294.04 h60
  text "REFERENCE:" at 14648.23,4290.1 h60
  text "X" at 15305.46,4290.01 h60
  text "AS SHOWN" at 15483.46,4290.1 h60
  text "X" at 16206.46,4290.1 h60
  text "OTHER" at 16632.46,4147.85 h60
  text "PTH COPPER THICKNESS:" at 14647.91,4144.32 h60
  text "X" at 15787.14,4144.32 h60
  text "20-30 um" at 15915.14,4144.32 h60
  text "BOARD FINISH:" at 14573.46,3996.73 h60
  text "SILKSCREEN:" at 14728.68,3886.6 h60
  text "X" at 15686.46,3886.6 h60
  text "TOP" at 15803.46,3886.6 h60
  text "X" at 16196.46,3886.6 h60
  text "BOTTOM" at 16314.46,3886.6 h60
  text "SILKSCREEN COLOR:" at 14728.68,3731.41 h60
  text "X" at 15685.46,3731.41 h60
  text "WHITE" at 15803.46,3731.41 h60
  text "OTHER" at 16314.46,3731.41 h60
  text "X" at 15816.46,3587.96 h60
  text "GREEN" at 15934.46,3587.96 h60
  text "OTHER" at 16552.46,3587.96 h60
  text "SOLDER RESIST COLOR:" at 14728.68,3581.1 h60
  text "X" at 15816.46,3433.71 h60
  text "MATTE" at 15934.46,3433.71 h60
  text "SEMI-GLOSS" at 16552,3433.07 h60
  text "IMMERSION GOLD (ENIG)" at 15634.46,3260.94 h60
  text "ENEPIG" at 16972,3253.72 h60
  text "SURFACE FINISH:" at 14573.46,3252.72 h60
  text "X" at 15456.46,3252.72 h60
  text "IMM. TIN/SILVER OR EQUIV" at 14903,3115.4 h60
  text "OTHER" at 16334.46,3111.47 h60
  text "ARRAY/PANEL:" at 14573.46,2956.09 h60
  text "CUT AND TRIM PER M1 BOARD OUTLINE" at 15634.46,2947.87 h60
  text "N.C. ROUTE" at 15634.46,2811.9 h60
  text "X" at 16322.46,2811.9 h60
  text "V. SCORE" at 16500.46,2811.9 h60
  text "CERTIFICATION:" at 14573.46,2682.77 h60
  text "MATERIALS AND WORKMANSHIP FOR ALL PCBS" at 15298.46,2682.77 h60
  text "TO MEET OR EXCEED THE REQUIREMENTS OF:" at 15298.46,2588.71 h60
  text "X" at 14935.97,2460.08 h60
  text "ANSI IPC-A-600F CLASS ->" at 15063.96,2460.08 h60
  text "X" at 16711.97,2460.08 h60
  text "2" at 16821.96,2460.08 h60
  text "1" at 16506.96,2458.58 h60
  text "3" at 17175.96,2458.58 h60
  text "X" at 15747.97,2312.39 h60
  text "RoHS" at 15875.96,2312.39 h60
  text "OTHER" at 16520.36,2312.39 h60
  text "PER ORDER" at 16917.42,2312.39 h60
  text "ALL BOARDS MUST MEET OR EXCEED UL94-V0 REQUIREMENTS." at 14601,2158.57 h60
  text "PCB MUST BEAR THE UL94V-0 UL REGISTERED MATERIAL ID NUMBER" at 14601,2042.5 h60
  text "ADDITIONAL REQUIREMENTS:" at 14573.46,1873.08 h60
  text "MICROSECTION:" at 14648.23,1765.95 h60
  text "YES" at 15553.96,1765.95 h60
  text "REQUIRED" at 16415.46,1621.62 h60
  text "BARE BOARD ELEC. TEST:" at 14648.23,1618.76 h60
  text "NONE" at 15953.96,1618.76 h60
  text "X" at 16297.46,1618.76 h60
  text "PER ORDER" at 17007.46,1618.76 h60
  text "XX MIL VIAS REQUIRE NON-CONDUCTIVE FILL AND PLANARIZE" at 14816.38,1413.82 h59
  text "XX MIL VIAS REQUIRE CONDUCTIVE FILL AND PLANARIZE" at 14824.38,1309.84 h60
  text "OUTER XX MIL TRACES REQUIRE 50 OHM SINGLE-ENDED IMPEDANCE" at 14823.39,1146.46 h58
  text "LAYER 2 & 3 (INNER LAYERS) XX MIL WIDE, XX MIL SPACE / TRACES REQUIRE 100 OHM DIFFERENTIAL IMPEDANCE" at 14815.39,910.74 h60
  text ".Layer_Name" at 577,-858.49 h60
M11 Gerber Information:
  lines w10: -292,-930.17 6308,-930.17 ; -292,-726.83 6310,-726.83 ; -292,-523.5 -292,-1133.5 3713,-1133.5 6310,-1133.5 6310,-523.5 -291.5,-523.5 -291.5,-1133.5 1284,-1133.5 ; 2173,-1133.5 2173,-523.5 ; 3440,-726.83 3440,-523.5 ; 4280,-726.83 4280,-523.5 ; 4902,-1140 4902,-937.17
  text "ALL ARTWORK VIEWED FROM TOP SIDE" at -228.5,-655.67 h60
  text "BOARD #:" at 2248,-655.67 h60
  text ".PRJ_Number" at 2793.5,-655.67 h60
  text "REV:" at 3638,-655.67 h60
  text ".PCB_Rev" at 3929.5,-655.67 h60
  text "SVN REV:" at 4476,-655.67 h60
  text ".VersionControl_RevNumber" at 4982,-655.67 h60
  text "LAYER NAME =" at -228.5,-858.49 h60
  text "TID #:" at 2248,-859 h60
  text ".TID" at 2793.5,-859 h60
  text "PLOT NAME =" at -228.5,-1064.34 h60
  text ".plot_File_Name" at 577,-1064.34 h60
  text "GENERATED    :" at 2250,-1064.34 h60
  text ".Print_Date" at 3119.5,-1064.34 h60
  text ".Print_Time" at 3848.5,-1064.34 h60
  text "TEXAS INSTRUMENTS" at 5113,-1064.34 h60
M12 Stackup:
  drawing of 196 lines, arcs and shapes, not listed
  text "Layer" at 15418.11,7794 h30
  text "Name" at 15543.25,7794 h30
  text "Material" at 15784.87,7794 h30
  text "Thickness" at 16002.09,7794 h30
  text "Constant" at 16180.55,7794 h30
  text "Board Layer Stack" at 16345.81,7794 h30
  text "Top Overlay" at 15543.25,7734 h30
  text "Top Solder" at 15543.25,7674 h30
  text "Solder Resist" at 15784.87,7674 h30
  text "0.40mil" at 16002.09,7674 h30
  text "3.5" at 16180.55,7674 h30
  text "1" at 15418.11,7614 h30
  text "Top Layer" at 15543.25,7614 h30
  text "Copper" at 15784.87,7614 h30
  text "2.80mil" at 16002.07,7614 h30
  text "Dielectric 2" at 15543.25,7554 h30
  text "FR-4" at 15784.87,7554 h30
  text "19.69mil" at 16002.09,7554 h30
  text "4.2" at 16180.55,7554 h30
  text "2" at 15418.09,7494 h30
  text "Signal Layer 1" at 15543.25,7494 h30
  text "Copper" at 15784.87,7494 h30
  text "2.80mil" at 16002.07,7494 h30
  text "Dielectric1" at 15543.25,7434 h30
  text "FR-4" at 15784.87,7434 h30
  text "59.20mil" at 16002.09,7434 h30
  text "4.8" at 16180.55,7434 h30
  text "3" at 15418.11,7374 h30
  text "Signal Layer 2" at 15543.25,7374 h30
  text "Copper" at 15784.87,7374 h30
  text "2.80mil" at 16002.07,7374 h30
  text "Dielectric 3" at 15543.25,7314 h30
  text "FR-4" at 15784.87,7314 h30
  text "19.69mil" at 16002.09,7314 h30
  text "4.2" at 16180.55,7314 h30
  text "4" at 15418.11,7254 h30
  text "Bottom Layer" at 15543.25,7254 h30
  text "Copper" at 15784.87,7254 h30
  text "2.80mil" at 16002.07,7254 h30
  text "Bottom Solder" at 15543.25,7194 h30
  text "Solder Resist" at 15784.87,7194 h30
  text "0.40mil" at 16002.09,7194 h30
  text "3.5" at 16180.55,7194 h30
  text "Bottom Overlay" at 15543.25,7134 h30
  text ".Layer_Name" at 577,-858.49 h60
M13 Component Bodies Top:
  text ".Layer_Name" at 577,-858.49 h60
M14 Component Bodies Bottom:
  text ".Layer_Name" at 577,-858.49 h60
M15 Courtyards Top:
  text ".Layer_Name" at 577,-858.49 h60
M16 Courtyards Bottom:
  text ".Layer_Name" at 577,-858.49 h60
Drill Drawing:
  drawing of 184 lines, arcs and shapes, not listed
  text "Symbol" at 12330.85,7741.48 h36
  text "Quantity" at 12480.45,7741.48 h36
  text "Finished Hole Size" at 12645.78,7741.48 h36
  text "Plated" at 12962.73,7741.48 h36
  text "Hole Type" at 13091.72,7741.48 h36
  text "Drill Layer Pair" at 13278.5,7741.48 h36
  text "Hole Tolerance" at 13638.47,7741.48 h36
  text "4" at 12480.45,7679.69 h30
  text "50.00mil (1.270mm)" at 12645.78,7679.69 h30
  text "NPTH" at 12962.73,7679.69 h30
  text "Round" at 13091.72,7679.69 h30
  text "Top Layer - Bottom Layer" at 13278.5,7679.69 h30
  text "J" at 12314.82,7669.69 h27.46
  text "15" at 12480.45,7617.9 h30
  text "236.22mil (6.000mm)" at 12645.78,7617.9 h30
  text "NPTH" at 12962.73,7617.9 h30
  text "Round" at 13091.72,7617.9 h30
  text "Top Layer - Bottom Layer" at 13278.5,7617.9 h30
  text "H" at 12314.82,7607.9 h27.46
  text "96" at 12480.45,7556.11 h30
  text "12.00mil (0.305mm)" at 12645.78,7556.11 h30
  text "PTH" at 12962.73,7556.11 h30
  text "Round" at 13091.72,7556.11 h30
  text "Top Layer - Bottom Layer" at 13278.5,7556.11 h30
  text "55" at 12480.45,7494.32 h30
  text "16.00mil (0.406mm)" at 12645.78,7494.32 h30
  text "PTH" at 12962.73,7494.32 h30
  text "Round" at 13091.72,7494.32 h30
  text "Top Layer - Bottom Layer" at 13278.5,7494.32 h30
  text "16" at 12480.45,7432.53 h30
  text "20.00mil (0.508mm)" at 12645.78,7432.53 h30
  text "PTH" at 12962.73,7432.53 h30
  text "Round" at 13091.72,7432.53 h30
  text "Top Layer - Bottom Layer" at 13278.5,7432.53 h30
  text "L" at 12314.82,7422.53 h27.46
  text "2769" at 12480.45,7370.74 h30
  text "28.00mil (0.711mm)" at 12645.78,7370.74 h30
  text "PTH" at 12962.73,7370.74 h30
  text "Round" at 13091.72,7370.74 h30
  text "Top Layer - Bottom Layer" at 13278.5,7370.74 h30
  text "1" at 12480.45,7308.95 h30
  text "30.00mil (0.762mm)" at 12645.78,7308.95 h30
  text "PTH" at 12962.73,7308.95 h30
  text "Round" at 13091.72,7308.95 h30
  text "Top Layer - Bottom Layer" at 13278.5,7308.95 h30
  text "K" at 12314.82,7298.96 h27.46
  text "2" at 12480.45,7247.16 h30
  text "33.07mil (0.840mm)" at 12645.78,7247.16 h30
  text "PTH" at 12962.73,7247.16 h30
  text "Round" at 13091.72,7247.16 h30
  text "Top Layer - Bottom Layer" at 13278.5,7247.16 h30
  text "5" at 12480.45,7185.37 h30
  text "33.07mil (0.840mm)" at 12645.78,7185.37 h30
  text "PTH" at 12962.73,7185.37 h30
  text "Round" at 13091.72,7185.37 h30
  text "Top Layer - Bottom Layer" at 13278.5,7185.37 h30
  text "M" at 12314.82,7175.38 h27.46
  text "12" at 12480.45,7123.58 h30
  text "35.43mil (0.900mm)" at 12645.78,7123.58 h30
  text "PTH" at 12962.73,7123.58 h30
  text "Round" at 13091.72,7123.58 h30
  text "Top Layer - Bottom Layer" at 13278.5,7123.58 h30
  text "+/-3.15mil" at 13638.47,7123.58 h30
  text "D" at 12314.82,7113.59 h27.46
  text "18" at 12480.45,7061.79 h30
  text "35.43mil (0.900mm)" at 12645.78,7061.79 h30
  text "PTH" at 12962.73,7061.79 h30
  text "Round" at 13091.72,7061.79 h30
  text "Top Layer - Bottom Layer" at 13278.5,7061.79 h30
  text "5" at 12480.45,7000 h30
  text "40.00mil (1.016mm)" at 12645.78,7000 h30
  text "PTH" at 12962.73,7000 h30
  text "Round" at 13091.72,7000 h30
  text "Top Layer - Bottom Layer" at 13278.5,7000 h30
  text "12" at 12480.45,6938.21 h30
  text "40.16mil (1.020mm)" at 12645.78,6938.21 h30
  text "PTH" at 12962.73,6938.21 h30
  text "Round" at 13091.72,6938.21 h30
  text "Top Layer - Bottom Layer" at 13278.5,6938.21 h30
  text "B" at 12314.82,6928.22 h27.46
  text "2" at 12480.45,6876.42 h30
  text "43.31mil (1.100mm)" at 12645.78,6876.42 h30
  text "PTH" at 12962.73,6876.42 h30
  text "Round" at 13091.72,6876.42 h30
  text "Top Layer - Bottom Layer" at 13278.5,6876.42 h30
  text "32" at 12480.45,6814.64 h30
  text "47.24mil (1.200mm)" at 12645.78,6814.64 h30
  text "PTH" at 12962.73,6814.64 h30
  text "Round" at 13091.72,6814.64 h30
  text "Top Layer - Bottom Layer" at 13278.5,6814.64 h30
  text "4" at 12480.45,6752.85 h30
  text "50.00mil (1.270mm)" at 12645.78,6752.85 h30
  text "PTH" at 12962.73,6752.85 h30
  text "Round" at 13091.72,6752.85 h30
  text "Top Layer - Bottom Layer" at 13278.5,6752.85 h30
  text "4" at 12480.45,6691.06 h30
  text "51.18mil (1.300mm)" at 12645.78,6691.06 h30
  text "PTH" at 12962.73,6691.06 h30
  text "Round" at 13091.72,6691.06 h30
  text "Top Layer - Bottom Layer" at 13278.5,6691.06 h30
  text "4" at 12480.45,6629.27 h30
  text "62.99mil (1.600mm)" at 12645.78,6629.27 h30
  text "PTH" at 12962.73,6629.27 h30
  text "Round" at 13091.72,6629.27 h30
  text "Top Layer - Bottom Layer" at 13278.5,6629.27 h30
  text "+/-5.91mil" at 13638.47,6629.27 h30
  text "4" at 12480.45,6567.48 h30
  text "63.00mil (1.600mm)" at 12645.78,6567.48 h30
  text "PTH" at 12962.73,6567.48 h30
  text "Round" at 13091.72,6567.48 h30
  text "Top Layer - Bottom Layer" at 13278.5,6567.48 h30
  text "A" at 12314.82,6557.48 h27.46
  text "16" at 12480.45,6505.69 h30
  text "70.08mil (1.780mm)" at 12645.78,6505.69 h30
  text "PTH" at 12962.73,6505.69 h30
  text "Round" at 13091.72,6505.69 h30
  text "Top Layer - Bottom Layer" at 13278.5,6505.69 h30
  text "E" at 12314.82,6495.69 h27.46
  text "8" at 12480.45,6443.9 h30
  text "75.00mil (1.905mm)" at 12645.78,6443.9 h30
  text "PTH" at 12962.73,6443.9 h30
  text "Round" at 13091.72,6443.9 h30
  text "Top Layer - Bottom Layer" at 13278.5,6443.9 h30
  text "4" at 12480.45,6382.11 h30
  text "86.61mil (2.200mm)" at 12645.78,6382.11 h30
  text "PTH" at 12962.73,6382.11 h30
  text "Round" at 13091.72,6382.11 h30
  text "Top Layer - Bottom Layer" at 13278.5,6382.11 h30
  text "G" at 12314.82,6372.11 h27.46
  text "4" at 12480.45,6320.32 h30
  text "102.36mil (2.600mm)" at 12645.78,6320.32 h30
  text "PTH" at 12962.73,6320.32 h30
  text "Round" at 13091.72,6320.32 h30
  text "Top Layer - Bottom Layer" at 13278.5,6320.32 h30
  text "F" at 12314.82,6310.32 h27.46
  text "4" at 12480.45,6258.53 h30
  text "157.48mil (4.000mm)" at 12645.78,6258.53 h30
  text "PTH" at 12962.73,6258.53 h30
  text "Round" at 13091.72,6258.53 h30
  text "Top Layer - Bottom Layer" at 13278.5,6258.53 h30
  text "7" at 12480.45,6196.74 h30
  text "216.54mil (5.500mm)" at 12645.78,6196.74 h30
  text "PTH" at 12962.73,6196.74 h30
  text "Round" at 13091.72,6196.74 h30
  text "Top Layer - Bottom Layer" at 13278.5,6196.74 h30
  text "C" at 12314.82,6186.75 h27.46
  text "6" at 12480.45,6134.95 h30
  text "260.00mil (6.604mm)" at 12645.78,6134.95 h30
  text "PTH" at 12962.73,6134.95 h30
  text "Round" at 13091.72,6134.95 h30
  text "Top Layer - Bottom Layer" at 13278.5,6134.95 h30
  text "8" at 12480.45,6073.16 h30
  text "80.00mil (2.032mm)" at 12645.78,6073.16 h30
  text "PTH" at 12962.73,6073.16 h30
  text "Rectangle" at 13091.72,6073.16 h30
  text "Top Layer - Bottom Layer" at 13278.5,6073.16 h30
  text "I" at 12319.4,6063.17 h27.46
  text "4" at 12480.45,6011.37 h30
  text "98.43mil (2.500mm)" at 12645.78,6011.37 h30
  text "PTH" at 12962.73,6011.37 h30
  text "Slot" at 13091.72,6011.37 h30
  text "Top Layer - Bottom Layer" at 13278.5,6011.37 h30
  text "3121 Total" at 12480.45,5949.58 h30
  text "Slot definitions :" at 12330.85,5906.33 h30
  text "Routed Path Length" at 12554.76,5906.33 h30
  text "= Calculated from tool start centre position to tool end centre position." at 12822.96,5906.33 h30
  text "Hole Length" at 12554.76,5881.62 h30
  text "= Routed Path Length + Tool Size = Slot length as defined in the PCB layout" at 12723.67,5881.62 h30
  text ".Layer_Name" at 577,-858.49 h60
M17 Embedded Cavity:
  text ".Layer_Name" at 577,-858.49 h60
M18 Embedded Assembly:
  text ".Layer_Name" at 577,-858.49 h60
M19 Embedded Keepout:
  text ".Layer_Name" at 577,-858.49 h60

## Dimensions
1961.56,5750.49 to 1961.56,5086.97 on M2 Board Dimensions
109,8474 to 0,0 on M2 Board Dimensions
6994.55,3462.02 to 6994.55,2615.56 on M2 Board Dimensions
0,-400 to 1000,-400 on M2 Board Dimensions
